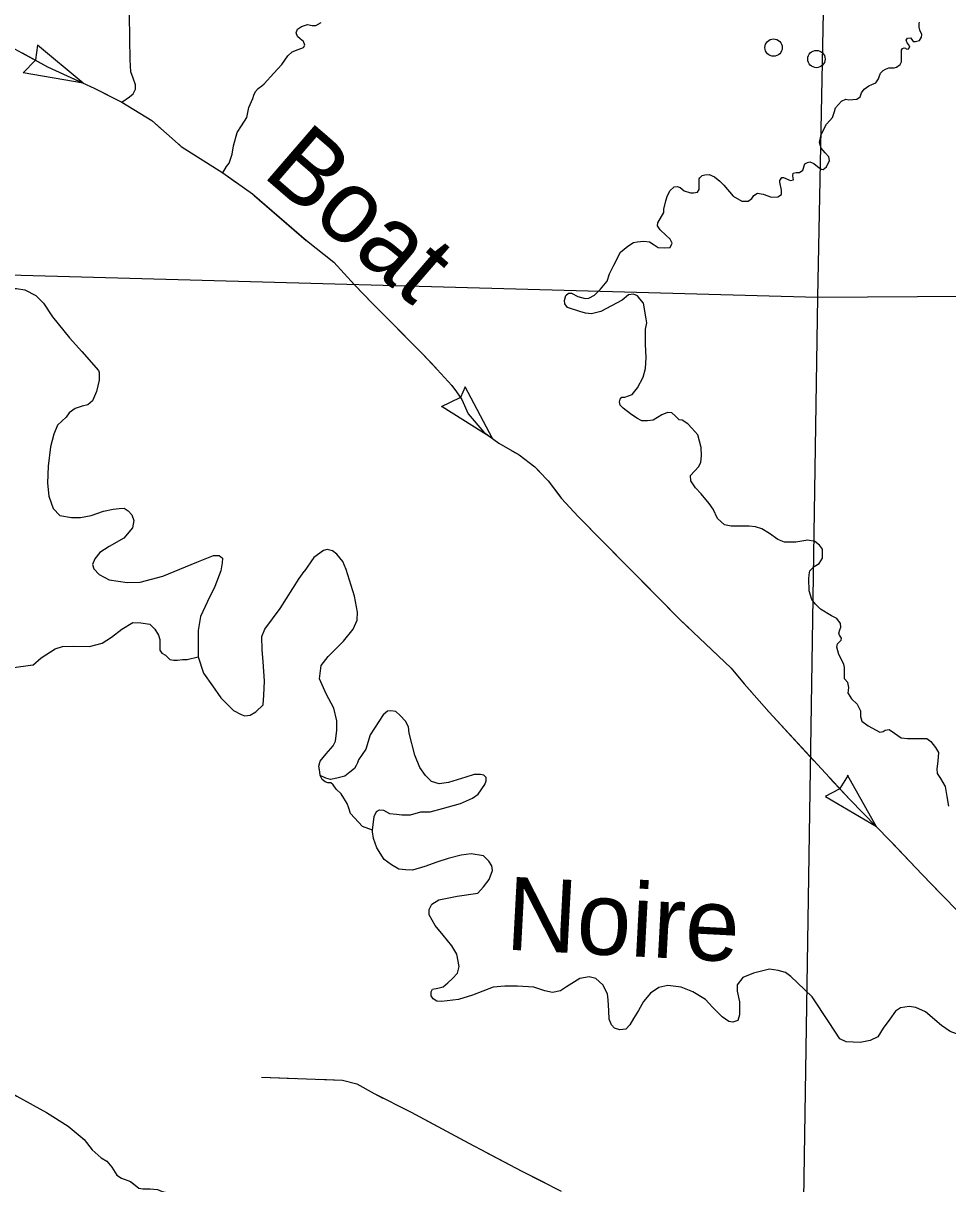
# Model space of a CAD drawing. Extents: x 1369979 to 1371646, y 379997 to 381064.
# Drawn here: x 1371044.2 to 1371106.9, y 380230.7 to 380309.4 of the extents above; entities that cross this region are included whole.
import ezdxf

# ---------------------------------------------------------------- set-up
doc = ezdxf.new("R2010")
doc.units = 0
doc.layers.add('R_Border Notes', color=7, linetype='Continuous')

msp = doc.modelspace()

# ---------------------------------------------------------------- linework, layer by layer
at = {"layer": 'R_Border Notes'}
for p, q in [((1371045.173, 380307.873), (1371045.033, 380306.859)), ((1371048.275, 380305.28), (1371045.173, 380307.873)), ((1371044.21, 380305.989), (1371045.027, 380306.847)), ((1371048.275, 380305.28), (1371044.21, 380305.989)), ((1371074.172, 380284.712), (1371073.841, 380283.992)), ((1371076.024, 380281.195), (1371074.175, 380284.701)), ((1371072.569, 380283.373), (1371073.83, 380283.984)), ((1371076.024, 380281.195), (1371072.594, 380283.347)), ((1371100.126, 380258.385), (1371099.555, 380257.48)), ((1371102.053, 380254.878), (1371100.078, 380258.381)), ((1371098.597, 380256.972), (1371099.545, 380257.471)), ((1371102.053, 380254.878), (1371098.591, 380256.925))]:
    msp.add_line(p, q, dxfattribs=at)
for points in [[(1371017.312, 380316.429), (1371020.815, 380315.192), (1371025.426, 380313.771), (1371028.531, 380312.529), (1371033.127, 380310.359), (1371034.785, 380309.63), (1371036.217, 380309.126), (1371037.784, 380309.066), (1371039.351, 380309.214), (1371040.178, 380309.126), (1371040.947, 380308.948), (1371042.869, 380308.031), (1371045.854, 380306.403), (1371049.009, 380304.939)], [(1371050.885, 380303.994), (1371051.415, 380304.373), (1371051.657, 380304.555), (1371051.809, 380304.889), (1371051.809, 380305.177), (1371051.657, 380305.631), (1371051.491, 380306.056), (1371051.46, 380306.874), (1371051.43, 380308.314), (1371051.415, 380309.951)], [(1371098.441, 380310.108), (1371098.041, 380290.785)], [(1371060.549, 380305.241), (1371061.183, 380305.972), (1371061.728, 380306.548), (1371062.152, 380307.139), (1371062.44, 380307.412), (1371062.834, 380307.578), (1371063.197, 380307.715), (1371063.288, 380307.866), (1371063.212, 380308.109), (1371062.985, 380308.291), (1371062.788, 380308.457), (1371062.697, 380308.7), (1371062.788, 380308.958), (1371063.076, 380309.124), (1371063.473, 380309.266)], [(1371063.473, 380309.266), (1371063.788, 380309.2), (1371064.045, 380309.2), (1371064.393, 380309.397)], [(1371099.684, 380304.075), (1371099.968, 380304.198), (1371100.18, 380304.167), (1371100.725, 380304.213), (1371100.937, 380304.365), (1371101.043, 380304.637), (1371101.224, 380304.88), (1371101.527, 380305.107), (1371101.739, 380305.198), (1371102.012, 380305.319), (1371102.178, 380305.577), (1371102.239, 380305.713), (1371102.33, 380305.956), (1371102.511, 380306.153), (1371102.663, 380306.244), (1371102.875, 380306.32), (1371103.238, 380306.32), (1371103.405, 380306.365), (1371103.662, 380306.547), (1371103.738, 380306.744), (1371103.753, 380307.032), (1371103.738, 380307.29), (1371103.738, 380307.517), (1371103.814, 380307.638), (1371103.92, 380307.684), (1371104.011, 380307.669), (1371104.056, 380307.608), (1371104.207, 380307.593), (1371104.313, 380307.729), (1371104.253, 380307.881), (1371104.132, 380308.017), (1371104.071, 380308.199), (1371104.147, 380308.336), (1371104.344, 380308.351), (1371104.45, 380308.245), (1371104.525, 380308.123), (1371104.692, 380308.108), (1371104.965, 380308.184), (1371105.101, 380308.396), (1371105.116, 380308.578), (1371104.995, 380308.881), (1371104.934, 380309.094), (1371104.949, 380309.321), (1371104.965, 380309.427)], [(1371044.123, 380307.347), (1371045.854, 380306.403), (1371048.275, 380305.28)], [(1371057.732, 380299.208), (1371057.99, 380299.648), (1371058.171, 380299.875), (1371058.368, 380300.466), (1371058.459, 380301.042), (1371058.701, 380301.952), (1371059.004, 380302.407), (1371059.352, 380302.967), (1371059.504, 380303.649), (1371059.761, 380304.241), (1371059.837, 380304.483), (1371059.958, 380304.726), (1371060.14, 380304.938), (1371060.382, 380305.105), (1371060.549, 380305.241)], [(1371049.009, 380304.939), (1371050.885, 380303.994), (1371052.911, 380302.749), (1371054.922, 380301.003), (1371057.732, 380299.208), (1371059.738, 380297.784)], [(1371049.668, 380304.607), (1371050.885, 380303.994), (1371051.701, 380303.493)], [(1371051.701, 380303.493), (1371052.911, 380302.749), (1371053.59, 380302.159)], [(1371097.053, 380299.4), (1371097.186, 380299.814), (1371097.363, 380299.918), (1371097.54, 380299.962), (1371097.792, 380299.844), (1371098.043, 380299.637), (1371098.294, 380299.459), (1371098.442, 380299.444), (1371098.649, 380299.622), (1371098.856, 380300.036), (1371098.826, 380300.288), (1371098.575, 380300.569), (1371098.294, 380300.879), (1371098.191, 380301.264), (1371098.309, 380301.811), (1371098.649, 380302.507), (1371098.886, 380302.758), (1371099.078, 380302.951), (1371099.196, 380303.365), (1371099.27, 380303.616), (1371099.684, 380304.075)], [(1371054.758, 380301.145), (1371054.922, 380301.003), (1371057.732, 380299.208), (1371058.621, 380298.578)], [(1371087.226, 380295.83), (1371087.625, 380296.521), (1371087.625, 380296.757), (1371087.773, 380297.32), (1371087.862, 380297.616), (1371088.039, 380297.985), (1371088.335, 380298.252), (1371088.541, 380298.296), (1371088.734, 380298.207), (1371089.014, 380298), (1371089.443, 380297.852), (1371089.65, 380297.852), (1371089.916, 380297.911), (1371090.02, 380298.074), (1371090.034, 380298.37), (1371090.034, 380298.518), (1371090.034, 380298.607), (1371090.034, 380298.799), (1371090.079, 380298.873), (1371090.241, 380299.036), (1371090.404, 380299.065), (1371090.714, 380299.095), (1371091.069, 380298.932), (1371091.439, 380298.651), (1371091.705, 380298.37)], [(1371091.705, 380298.37), (1371092.337, 380297.63), (1371092.914, 380297.29), (1371093.342, 380297.29), (1371093.594, 380297.482), (1371093.742, 380297.675), (1371093.993, 380297.837), (1371094.362, 380297.764), (1371094.924, 380297.556), (1371095.368, 380297.586), (1371095.604, 380297.734), (1371095.619, 380298.03), (1371095.501, 380298.577), (1371095.486, 380298.696), (1371095.634, 380298.888), (1371095.752, 380298.903), (1371096.107, 380298.74), (1371096.225, 380298.696), (1371096.417, 380298.74), (1371096.387, 380299.006), (1371096.402, 380299.199), (1371096.594, 380299.243), (1371096.831, 380299.243), (1371097.053, 380299.4)], [(1371059.738, 380297.784), (1371063.404, 380294.618), (1371065.266, 380293.153), (1371066.658, 380291.628)], [(1371059.871, 380297.669), (1371063.384, 380294.636)], [(1371084.24, 380292.96), (1371084.698, 380293.832), (1371085.201, 380294.247), (1371085.57, 380294.483), (1371085.822, 380294.528), (1371086.28, 380294.572), (1371086.664, 380294.543), (1371086.975, 380294.336), (1371087.256, 380294.143), (1371087.684, 380294.128), (1371088.054, 380294.143), (1371088.202, 380294.454), (1371088.068, 380294.72), (1371087.758, 380294.986), (1371087.389, 380295.342), (1371087.196, 380295.623), (1371087.226, 380295.83)], [(1371064.599, 380293.678), (1371065.266, 380293.153), (1371066.658, 380291.628), (1371067.849, 380290.378)], [(1371035.87, 380292.511), (1371098.041, 380290.785)], [(1371037.722, 380292.755), (1371038.235, 380292.71), (1371038.708, 380292.577), (1371039.536, 380292.119), (1371040.083, 380291.749), (1371040.541, 380291.675), (1371041.162, 380291.793), (1371041.561, 380291.852), (1371041.975, 380291.852), (1371042.389, 380291.793), (1371042.906, 380291.586), (1371043.453, 380291.364), (1371043.749, 380291.379), (1371044.31, 380291.275), (1371045.049, 380290.891), (1371045.581, 380290.388), (1371046.187, 380289.455), (1371047.34, 380288.02)], [(1371086.443, 380289.32), (1371086.25, 380290.385), (1371086.014, 380290.681), (1371085.836, 380290.873), (1371085.585, 380290.977), (1371085.23, 380290.933), (1371084.802, 380290.592), (1371083.353, 380289.823), (1371082.732, 380289.66), (1371082.318, 380289.69), (1371081.949, 380289.808), (1371081.106, 380290.089), (1371080.929, 380290.341), (1371080.899, 380290.548), (1371080.988, 380290.903), (1371081.166, 380291.066), (1371081.372, 380291.066), (1371081.801, 380290.829), (1371082.289, 380290.696), (1371082.54, 380290.726), (1371082.939, 380290.918), (1371083.338, 380291.332), (1371083.782, 380291.88), (1371083.944, 380292.368), (1371084.24, 380292.96)], [(1371066.658, 380291.628), (1371067.899, 380290.326), (1371071.269, 380286.953), (1371072.275, 380285.888)], [(1371098.041, 380290.785), (1371128.53, 380290.993)], [(1371098.041, 380290.785), (1371097.105, 380229.657)], [(1371068.941, 380289.283), (1371071.269, 380286.953), (1371072.194, 380285.973)], [(1371086.398, 380285.947), (1371086.428, 380286.686), (1371086.398, 380287.574), (1371086.398, 380288.61), (1371086.472, 380289.054), (1371086.443, 380289.32)], [(1371047.34, 380288.02), (1371048.18, 380287.094), (1371049.303, 380285.822), (1371049.362, 380285.689), (1371049.362, 380285.156), (1371049.17, 380284.401), (1371048.904, 380283.765), (1371048.579, 380283.484), (1371048.195, 380283.395), (1371047.929, 380283.302), (1371047.722, 380283.243), (1371047.323, 380282.937), (1371047.116, 380282.641)], [(1371072.275, 380285.888), (1371073.25, 380284.793), (1371073.575, 380284.378), (1371073.93, 380283.846), (1371074.373, 380282.869), (1371075.438, 380281.627), (1371076.443, 380280.887), (1371077.832, 380280.088), (1371078.897, 380279.289), (1371079.213, 380278.951)], [(1371089.77, 380277.855), (1371089.473, 380278.327), (1371089.443, 380278.697), (1371090.005, 380279.319), (1371090.138, 380279.6), (1371090.197, 380280.029), (1371090.153, 380280.591), (1371089.946, 380281.464), (1371089.532, 380281.908), (1371089.251, 380282.189), (1371088.881, 380282.44), (1371088.675, 380282.47), (1371088.408, 380282.751), (1371088.172, 380282.943), (1371087.891, 380282.973), (1371087.507, 380282.81), (1371086.901, 380282.455), (1371086.531, 380282.411), (1371086.147, 380282.396), (1371085.807, 380282.573), (1371085.363, 380282.869), (1371084.876, 380283.254), (1371084.669, 380283.476), (1371084.624, 380283.698), (1371084.669, 380283.875), (1371084.787, 380284.009), (1371084.979, 380284.009), (1371085.482, 380284.186), (1371085.836, 380284.645), (1371086.221, 380285.355), (1371086.398, 380285.947)], [(1371073.225, 380284.821), (1371073.25, 380284.793), (1371073.575, 380284.378), (1371073.93, 380283.846), (1371074.373, 380282.869), (1371075.438, 380281.627), (1371076.024, 380281.195)], [(1371047.116, 380282.641), (1371046.524, 380282.119), (1371046.273, 380281.497), (1371046.051, 380280.639), (1371045.889, 380279.322), (1371045.844, 380278.183), (1371045.948, 380277.295), (1371046.229, 380276.467), (1371046.687, 380275.979), (1371047.485, 380275.846), (1371048.076, 380275.846), (1371048.816, 380275.993), (1371049.643, 380276.289), (1371050.294, 380276.423), (1371050.708, 380276.467), (1371051.048, 380276.482), (1371051.314, 380276.304), (1371051.565, 380276.038), (1371051.713, 380275.653), (1371051.609, 380275.15)], [(1371077.333, 380280.375), (1371077.832, 380280.088), (1371078.897, 380279.289), (1371079.179, 380278.987)], [(1371079.179, 380278.987), (1371079.213, 380278.951), (1371079.783, 380278.342), (1371080.649, 380277.196)], [(1371079.213, 380278.951), (1371079.783, 380278.342), (1371080.7, 380277.129), (1371081.823, 380275.916)], [(1371093.415, 380275.257), (1371092.207, 380275.253), (1371091.734, 380275.356), (1371091.276, 380275.785), (1371090.966, 380276.422), (1371090.7, 380276.806), (1371090.167, 380277.457), (1371089.77, 380277.855)], [(1371081.694, 380276.055), (1371081.823, 380275.916), (1371084.952, 380272.751)], [(1371081.823, 380275.916), (1371088.738, 380268.922), (1371092.197, 380265.638), (1371093.084, 380264.572), (1371094.769, 380262.649), (1371100.238, 380256.731), (1371102.945, 380253.967)], [(1371051.609, 380275.15), (1371051.033, 380274.449), (1371050.028, 380273.887), (1371049.407, 380273.472), (1371049.052, 380273.043), (1371048.889, 380272.673), (1371048.993, 380272.378), (1371049.362, 380271.978), (1371050.028, 380271.623), (1371051.24, 380271.445), (1371052.127, 380271.475), (1371053.679, 380271.875), (1371055.97, 380272.821), (1371057.093, 380273.265), (1371057.492, 380273.265), (1371057.714, 380273.103), (1371057.684, 380272.777), (1371057.61, 380272.244), (1371057.182, 380271.164)], [(1371098.382, 380273.093), (1371098.396, 380273.704), (1371098.175, 380273.97), (1371097.879, 380274.236), (1371097.391, 380274.325), (1371096.578, 380274.177), (1371095.81, 380274.177), (1371095.351, 380274.37), (1371094.804, 380274.769), (1371094.272, 380275.08), (1371093.858, 380275.228), (1371093.415, 380275.257)], [(1371065.87, 380272.862), (1371065.456, 380273.376), (1371065.175, 380273.598), (1371064.82, 380273.686), (1371064.554, 380273.612), (1371063.904, 380273.139), (1371063.253, 380272.191)], [(1371064.746, 380263.904), (1371064.288, 380264.928), (1371064.406, 380265.817), (1371064.88, 380266.423), (1371065.915, 380267.474), (1371066.58, 380268.274), (1371066.832, 380268.895), (1371066.876, 380269.428), (1371066.669, 380270.523), (1371066.107, 380272.329), (1371065.87, 380272.862)], [(1371100.126, 380263.929), (1371100.141, 380264.157), (1371100.17, 380264.334), (1371100.111, 380264.66), (1371099.889, 380264.911), (1371099.874, 380265.103), (1371099.889, 380265.385), (1371099.889, 380265.695), (1371099.83, 380265.917), (1371099.505, 380266.568), (1371099.357, 380267.071), (1371099.416, 380267.293), (1371099.653, 380267.545), (1371099.682, 380267.678), (1371099.535, 380267.87), (1371099.49, 380268.018), (1371099.564, 380268.24), (1371099.623, 380268.418), (1371099.608, 380268.669), (1371099.357, 380268.995), (1371098.988, 380269.187), (1371098.249, 380269.631), (1371097.909, 380269.971), (1371097.672, 380270.297), (1371097.495, 380270.888), (1371097.465, 380271.702), (1371097.48, 380271.968), (1371097.539, 380272.235), (1371097.835, 380272.531), (1371098.16, 380272.723), (1371098.382, 380273.093)], [(1371057.182, 380271.164), (1371056.692, 380270.152), (1371056.219, 380269.146), (1371056.072, 380268.185), (1371056.072, 380266.883), (1371056.072, 380266.409), (1371056.426, 380265.3), (1371057.032, 380264.442), (1371057.594, 380263.628), (1371058.451, 380262.77), (1371058.969, 380262.489), (1371059.235, 380262.4), (1371059.59, 380262.459), (1371059.974, 380262.681), (1371060.462, 380263.154), (1371060.506, 380263.805), (1371060.55, 380264.752), (1371060.462, 380266.084), (1371060.403, 380266.883), (1371060.373, 380267.785), (1371060.592, 380268.273), (1371061.612, 380269.694), (1371062.913, 380271.718), (1371063.253, 380272.191)], [(1371086.04, 380271.651), (1371088.738, 380268.922), (1371089.32, 380268.369)], [(1371044.853, 380265.847), (1371045.429, 380266.335), (1371046.375, 380266.957), (1371046.863, 380267.119), (1371047.587, 380267.134), (1371048.696, 380267.105), (1371049.553, 380267.341), (1371050.189, 380267.741), (1371050.898, 380268.288), (1371051.637, 380268.732), (1371052.184, 380268.717), (1371052.79, 380268.614), (1371053.115, 380268.273), (1371053.367, 380267.874), (1371053.47, 380267.578), (1371053.47, 380267.075), (1371053.47, 380266.868), (1371053.603, 380266.661), (1371053.854, 380266.513), (1371054.135, 380266.217), (1371054.416, 380266.187), (1371054.667, 380266.187), (1371055.007, 380266.217), (1371055.318, 380266.232), (1371056.072, 380266.409)], [(1371090.442, 380267.304), (1371092.197, 380265.638), (1371093.084, 380264.572), (1371093.634, 380263.945)], [(1371044.853, 380265.847), (1371044.371, 380265.773), (1371043.218, 380265.625)], [(1371064.329, 380259.332), (1371064.732, 380259.834), (1371065.22, 380260.382), (1371065.382, 380260.692), (1371065.471, 380261.447), (1371065.471, 380262.069), (1371065.264, 380262.927), (1371064.746, 380263.904)], [(1371100.126, 380263.929), (1371100.362, 380263.559), (1371100.747, 380263.189), (1371100.968, 380262.745), (1371100.954, 380262.375), (1371101.057, 380262.05), (1371101.486, 380261.739), (1371102.284, 380261.31), (1371102.491, 380261.34), (1371102.639, 380261.428), (1371102.905, 380261.488), (1371103.259, 380261.236), (1371103.718, 380260.911), (1371104.161, 380260.866), (1371104.945, 380260.866), (1371105.462, 380260.866), (1371105.743, 380260.674), (1371106.053, 380260.26), (1371106.26, 380259.934), (1371106.201, 380259.342), (1371106.142, 380258.824), (1371106.171, 380258.499), (1371106.378, 380258.173), (1371106.704, 380257.611), (1371106.807, 380256.946), (1371106.94, 380256.295)], [(1371067.876, 380254.661), (1371067.997, 380255.587), (1371068.159, 380255.928), (1371068.367, 380256.046), (1371068.633, 380256.017), (1371069.032, 380255.795), (1371069.52, 380255.735), (1371069.86, 380255.691), (1371070.466, 380255.706), (1371071.161, 380255.898), (1371071.797, 380255.913), (1371072.625, 380256.12), (1371073.838, 380256.475), (1371074.666, 380256.831), (1371075.036, 380257.097), (1371075.494, 380257.748), (1371075.598, 380258), (1371075.583, 380258.222), (1371075.435, 380258.385), (1371075.198, 380258.444), (1371074.77, 380258.429), (1371074.208, 380258.252), (1371073.039, 380257.882), (1371072.404, 380257.808), (1371071.871, 380257.956), (1371071.472, 380258.355), (1371071.102, 380258.903), (1371070.762, 380259.747), (1371070.363, 380261.227), (1371070.333, 380261.671), (1371070.111, 380262.056), (1371069.757, 380262.44), (1371069.461, 380262.707), (1371069.121, 380262.751), (1371068.899, 380262.722), (1371068.603, 380262.485), (1371067.731, 380261.123), (1371067.435, 380260.146)], [(1371094.653, 380262.781), (1371094.769, 380262.649), (1371097.799, 380259.37)], [(1371067.435, 380260.146), (1371066.932, 380259.436), (1371066.858, 380259.229), (1371066.769, 380259.036), (1371066.651, 380258.829), (1371066.341, 380258.592), (1371066, 380258.311), (1371065.453, 380258.178), (1371065.039, 380258.089)], [(1371067.876, 380254.661), (1371067.213, 380254.907), (1371066.4, 380255.78), (1371066.281, 380256.15), (1371066.163, 380256.475), (1371065.941, 380256.831), (1371065.749, 380257.112), (1371065.409, 380257.438), (1371065.217, 380257.734), (1371065.054, 380257.867), (1371064.847, 380257.867), (1371064.67, 380257.941), (1371064.477, 380258.104), (1371064.329, 380258.37), (1371064.315, 380258.607), (1371064.241, 380258.992), (1371064.329, 380259.332)], [(1371065.039, 380258.089), (1371064.714, 380258.192), (1371064.329, 380258.37)], [(1371098.849, 380258.234), (1371100.238, 380256.731), (1371102.053, 380254.878)], [(1371073.628, 380250.182), (1371075.018, 380250.398), (1371075.417, 380250.812), (1371075.787, 380251.316), (1371076.009, 380251.923), (1371075.964, 380252.233), (1371075.772, 380252.559), (1371075.417, 380252.914), (1371074.56, 380253.062), (1371073.894, 380252.959), (1371073.007, 380252.737), (1371072.238, 380252.5), (1371071.425, 380252.189), (1371070.596, 380251.952), (1371070.123, 380251.967), (1371069.665, 380252.011), (1371069.162, 380252.307), (1371068.674, 380252.677), (1371068.186, 380253.462), (1371067.949, 380254.098), (1371067.89, 380254.542), (1371067.876, 380254.661)], [(1371102.945, 380253.967), (1371105.177, 380251.63), (1371106.477, 380250.269), (1371107.616, 380249.129), (1371108.441, 380248.009)], [(1371103.133, 380253.77), (1371104.735, 380252.092)], [(1371104.735, 380252.092), (1371105.177, 380251.63), (1371106.338, 380250.414)], [(1371080.617, 380243.769), (1371080.075, 380243.665), (1371079.558, 380243.769), (1371078.818, 380244.02), (1371077.709, 380244.094), (1371076.852, 380244.094), (1371076.053, 380244.02), (1371074.663, 380243.473), (1371073.702, 380243.177), (1371072.563, 380243.058), (1371072.253, 380243.073), (1371071.987, 380243.236), (1371071.853, 380243.443), (1371071.853, 380243.695), (1371071.942, 380243.887), (1371072.312, 380243.946), (1371072.667, 380244.035), (1371072.992, 380244.316), (1371073.303, 380244.597), (1371073.643, 380244.968), (1371073.761, 380245.426), (1371073.598, 380246.26), (1371073.258, 380246.822), (1371072.667, 380247.533), (1371072.12, 380248.199), (1371071.72, 380248.924), (1371071.72, 380249.294), (1371071.898, 380249.649), (1371072.371, 380249.945), (1371073.628, 380250.182)], [(1371094.794, 380245.234), (1371093.719, 380244.968), (1371092.994, 380244.686), (1371092.609, 380244.183), (1371092.595, 380243.739), (1371092.772, 380243.029), (1371092.772, 380242.155), (1371092.639, 380241.77), (1371092.314, 380241.637), (1371092.033, 380241.696), (1371091.589, 380242.007), (1371090.924, 380242.658), (1371090.45, 380243.177), (1371089.608, 380243.695), (1371088.809, 380244.02), (1371087.907, 380244.124), (1371087.301, 380243.991), (1371086.724, 380243.606), (1371086.251, 380243.043), (1371085.911, 380242.436), (1371085.571, 380241.889), (1371085.319, 380241.46), (1371085.053, 380241.164), (1371084.639, 380241.134), (1371084.299, 380241.252), (1371084.092, 380241.474), (1371083.929, 380241.859), (1371083.9, 380242.407), (1371083.855, 380243.162), (1371083.811, 380243.561), (1371083.5, 380244.183), (1371083.027, 380244.597), (1371082.569, 380244.716), (1371081.933, 380244.597), (1371081.031, 380244.05), (1371080.617, 380243.769)], [(1371108.869, 380241.424), (1371108.25, 380240.942), (1371107.467, 380240.853), (1371107.053, 380241.016), (1371106.446, 380241.43), (1371105.367, 380242.348), (1371104.716, 380242.644), (1371104.273, 380242.718), (1371103.666, 380242.614), (1371103.341, 380242.392), (1371102.956, 380241.844), (1371102.513, 380241.238), (1371102.143, 380240.66), (1371101.611, 380240.394), (1371100.945, 380240.261), (1371099.984, 380240.305), (1371099.555, 380240.527), (1371098.831, 380241.622), (1371097.692, 380243.354), (1371096.701, 380244.316), (1371096.243, 380244.745), (1371095.873, 380245.012), (1371095.385, 380245.16), (1371094.794, 380245.234)], [(1371039.844, 380238.609), (1371042.061, 380237.589), (1371043.761, 380236.642), (1371045.786, 380235.532), (1371047.249, 380234.6), (1371048.328, 380233.697), (1371048.875, 380233.002), (1371049.477, 380232.459)], [(1371060.355, 380237.916), (1371065.856, 380237.724), (1371066.818, 380237.457), (1371067.986, 380236.806), (1371070.495, 380235.539)], [(1371060.355, 380237.916), (1371062.674, 380237.835)], [(1371064.22, 380237.781), (1371065.856, 380237.724), (1371066.818, 380237.457), (1371067.986, 380236.806), (1371068.582, 380236.505)], [(1371043.059, 380237.033), (1371043.761, 380236.642), (1371045.786, 380235.532), (1371047.075, 380234.711)], [(1371069.963, 380235.808), (1371070.495, 380235.539), (1371074.065, 380233.638)], [(1371070.495, 380235.539), (1371074.414, 380233.452), (1371078.007, 380231.558), (1371080.68, 380230.205)], [(1371048.277, 380233.74), (1371048.328, 380233.697), (1371048.875, 380233.002), (1371049.477, 380232.459), (1371049.861, 380232.237), (1371050.216, 380231.823), (1371050.541, 380231.276), (1371050.866, 380231.068), (1371051.487, 380230.846), (1371051.645, 380230.712)], [(1371075.433, 380232.915), (1371078.007, 380231.558), (1371079.551, 380230.776)], [(1371049.477, 380232.459), (1371049.861, 380232.237), (1371050.216, 380231.823), (1371050.541, 380231.276), (1371050.866, 380231.068), (1371051.487, 380230.846), (1371051.782, 380230.595), (1371052.049, 380230.388), (1371052.315, 380230.358), (1371052.802, 380230.343), (1371053.305, 380230.299), (1371053.63, 380230.181), (1371054.428, 380230.018), (1371055.433, 380229.9), (1371056.069, 380229.781), (1371056.513, 380229.589), (1371056.897, 380229.293), (1371057.237, 380229.086), (1371057.532, 380229.042), (1371057.946, 380228.968), (1371058.478, 380228.953), (1371058.907, 380228.731), (1371059.365, 380228.45), (1371060.337, 380227.926)]]:
    msp.add_lwpolyline(points, dxfattribs=at)
for centre in [(1371095.072, 380307.698), (1371097.978, 380306.924)]:
    msp.add_circle(centre, 0.586, dxfattribs=at)

# ---------------------------------------------------------------- texts
for s, rotation, p in [('Boat', 319.21013, (1371060.326, 380299.055)), ('Noire', 356.9524, (1371076.859, 380246.572))]:
    msp.add_text(s, height=4.95, rotation=rotation, dxfattribs=at).set_placement(p)

doc.saveas('drawing.dxf')
